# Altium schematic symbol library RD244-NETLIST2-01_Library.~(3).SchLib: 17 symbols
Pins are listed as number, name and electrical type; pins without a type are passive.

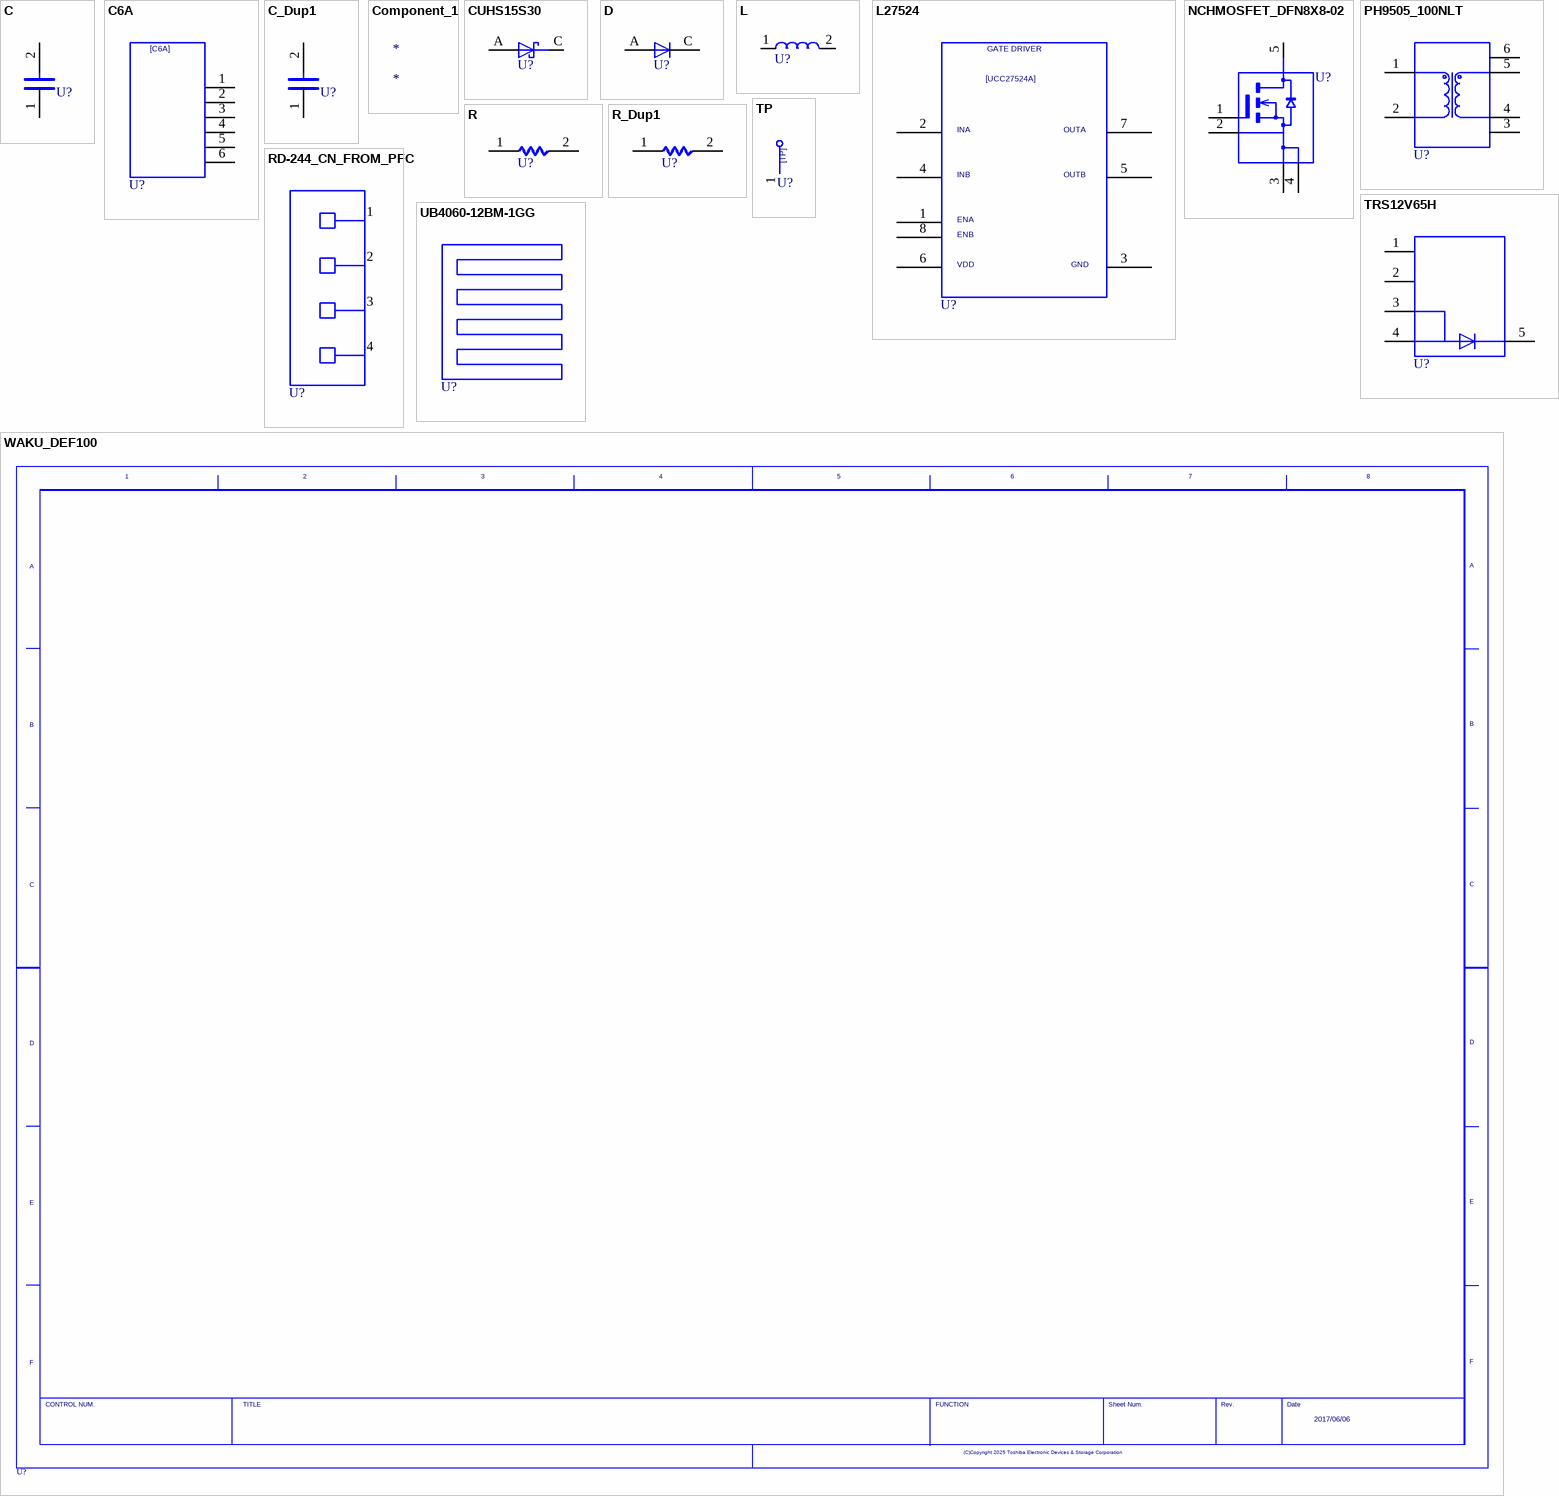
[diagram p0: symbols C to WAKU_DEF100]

## C
designator U?  (value not drawn)
OriginalSymbolOrigin: (2540,7620); Altium-Right: 20; Altium-Bottom: 10
pins: 1, 2

## C6A
designator U?  (value not drawn)
SAVEAREA0: -13050,-324,32905,28692; SAVECOUNT: 22; TIME: 13:28:28; UPDATEUSER: tomizawa-y; UPDATETIME: 10:39:55; OriginalSymbolOrigin: (2540,25400); Altium-Right: 50; Altium-Bottom: 90
pins: 1, 2, 3, 4, 5, 6

## C_Dup1
designator U?, comment C  (value not drawn)
OriginalSymbolOrigin: (2540,7620); Altium-Right: 20; Altium-Bottom: 10
pins: 1, 2

## Component_1
designator *

## CUHS15S30
designator U?  (value not drawn)
SAVEAREA0: -4630,-153,17114,13055; TIME: 14:49:55; UPDATEUSER: t4887876; UPDATETIME: 17:19:09; SAVECOUNT: 10; OriginalSymbolOrigin: (5080,5080); Altium-Right: 20
pins: A, C

## D
designator U?  (value not drawn)
SAVEAREA0: -225,-91,12804,7836; SAVECOUNT: 3; TIME: 14:49:55; UPDATEUSER: 19870035; UPDATETIME: 14:20:16; OriginalSymbolOrigin: (5080,5080); Altium-Right: 10; Altium-Bottom: 20
pins: A, C

## L
designator U?  (value not drawn)
OriginalSymbolOrigin: (2540,5080); Altium-Right: 30; Altium-Bottom: 20
pins: 1, 2

## L27524
designator U?  (value not drawn)
SAVEAREA0: -24347,-591,50370,48694; SAVECOUNT: 22; TIME: 15:02:55; UPDATEUSER: cae; UPDATETIME: 14:54:38; OriginalSymbolOrigin: (7620,45720); Altium-Right: 110; Altium-Bottom: 170
pins: 1, 2, 3, 4, 5, 6, 7, 8

## NCHMOSFET_DFN8X8-02
designator U?, comment NchMOSFET_DFN8x8-02  (value not drawn)
SAVECOUNT: 22; SAVEAREA0: -7027,-292,21786,15988; VAL3: ※型名を記入する(DFN8x8); TIME: 18:23:27; UPDATEUSER: t5459927; UPDATETIME: 10:08:10; CHIPSET: DFN8x8; VAL1: ※定格電圧を記入する; VAL2: ※定格電流を記入する; OriginalSymbolOrigin: (5080,22860); Altium-Right: 50; Altium-Bottom: 70
pins: 1, 2, 3, 4, 5

## PH9505_100NLT
designator U?  (value not drawn)
TIME: 20:40:33; UPDATEUSER: t4887876; UPDATETIME: 09:36:55; SAVECOUNT: 7; VAL3: PH9505.100NLT; VAL1: 1:100; VAL2: 30A; OriginalSymbolOrigin: (5080,17780); Altium-Right: 50; Altium-Bottom: 70
pins: 1, 2, 3, 4, 5, 6

## R
designator U?  (value not drawn)
OriginalSymbolOrigin: (5080,5080); Altium-Right: 20
pins: 1, 2

## R_Dup1
designator U?, comment R  (value not drawn)
OriginalSymbolOrigin: (5080,5080); Altium-Right: 20
pins: 1, 2

## RD-244_CN_FROM_PFC
designator U?, comment RD-244_CN_from_PFC  (value not drawn)
TIME: 11:34:46; UPDATEUSER: t4887876; UPDATETIME: 21:48:48; SAVECOUNT: 35; SAVEAREA0: -20981,-344,43891,33349; VAL3: PCB_Pad; OriginalSymbolOrigin: (0,33020); Altium-Right: 50; Altium-Bottom: 130
pins: 1, 2, 3, 4

## TP
designator U?  (value not drawn)
TIME: 16:12:21; UPDATEUSER: fukuda-y; UPDATETIME: 16:18:11; SAVECOUNT: 2; SAVEAREA0: -242,-92,12810,7836; OriginalSymbolOrigin: (0,7620); Altium-Right: 20; Altium-Bottom: 30
pins: 1

## TRS12V65H
designator U?  (value not drawn)
SAVEAREA0: -33193,-13687,53697,33858; TIME: 14:49:55; UPDATEUSER: t4887876; UPDATETIME: 12:31:26; SAVECOUNT: 38; VAL1: 650V; VAL2: 12A; OriginalSymbolOrigin: (5080,20320); Altium-Right: 60; Altium-Bottom: 80
pins: 1, 2, 3, 4, 5

## UB4060-12BM-1GG
designator U?  (value not drawn)
TIME: 14:03:26; UPDATEUSER: t4887876; UPDATETIME: 11:07:19; SAVECOUNT: 66; SAVEAREA0: -22316,-9081,43667,39223; VAL2: W40mm*L60mm*H12mm; OriginalSymbolOrigin: (5080,21590); Altium-Right: 80; Altium-Bottom: 90

## WAKU_DEF100
designator U?  DATE: 2017/06/06  (hidden comment: WAKU_DEF100)
PLOTTIME: HH:MM; SAVEAREA0: -63393,-16950,474261,314592; TIME: 14:30:25; UPDATEUSER: t5459927; UPDATETIME: 15:27:53; SAVECOUNT: 8; OriginalSymbolOrigin: (10160,284480); Altium-Right: 1570; Altium-Bottom: 1070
